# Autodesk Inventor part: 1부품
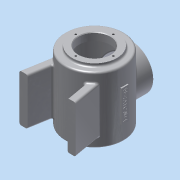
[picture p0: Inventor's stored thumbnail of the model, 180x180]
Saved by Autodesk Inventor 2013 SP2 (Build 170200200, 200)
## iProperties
Created: 2015-01
Part Number: 1부품
Material: 알루미늄 6061
Document SubType Name: Modeling
Designer: dgall
Density: 2.71 g/cm^3
Author: dgall
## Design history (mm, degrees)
sketch "스케치1"
  geometry: C1 r 50 at (0, 0); 1 further point
  constraints: 1 centre point, 1 coincident
  dimensions: "d4" = 100 diameter of C1
extrude "돌출1" new body sketch "스케치1" distance "d1" = 112; taper "d2" = 0 deg
node "작업 평면1"
sketch "스케치2"
  geometry: C1 r 38 at (0, 0); 1 further point
  constraints: 1 centre point, 1 coincident
  dimensions: "d7" = 38 radius of C1
extrude "돌출2" join sketch "스케치2" distance "d9" = 122; taper "d10" = 0 deg
sketch "스케치3"
  geometry: C1 r 38 at (0, 0) reference; C2 r 27 at (0, 0)
  constraints: 1 centre point, 1 coincident
  dimensions: "d11" = 27 radius of C2
extrude "돌출3" cut sketch "스케치3" distance "d12" = 122; taper "d13" = 0 deg
node "작업 평면2"
sketch "스케치4"
  geometry: C1 r 45 at (0, 0); 1 further point
  constraints: 1 centre point, 1 coincident
  dimensions: "d15" = 45 radius of C1
extrude "돌출4" cut sketch "스케치4" distance "d16" = 97; taper "d17" = 0 deg
node "작업 평면3"
sketch "스케치5"
  geometry: L1 (-38, 117)-(38, 117) reference; L2 (-50, 0)-(-50, 112) reference; C1 r 38 at (0, 55); 3 further points
  constraints: 2 midpoint, 1 centre point, 1 vertical alignment
  dimensions: "d81" = 38 radius of C1; "d82" = 62 distance from line of L1 C1.centre
extrude "돌출5" join sketch "스케치5" stored distance "d20" = 97; taper "d21" = 0 deg
sketch "스케치8"
  geometry: C1 r 27 at (0, 0) reference; 1 further point
  constraints: 1 vertical alignment
  dimensions: "d37" = 32 distance of C1.centre point (0, 32)
hole "구멍2" sketch "스케치8" at (0, 32) diameter "d38" = 3.242; stored, may be unused: countersink angle "d42" = 90 deg, drill point angle "d44" = 118 deg; dims "d39" = 8, "d40" = 4, "d41" = 2, "d43" = 10
node "작업 평면4"
node "작업 평면5"
sketch "스케치9"
  geometry: L1 (-38, 117)-(38, 117) reference; L2 (6, 82)-(-6, 82); L3 (-6, 82)-(-6, 28); L4 (-6, 28)-(6, 28); L5 (6, 28)-(6, 82); 5 further points
  constraints: 8 end point, 3 midpoint, 2 coincident, 2 parallel, 1 horizontal, 1 perpendicular, 1 vertical alignment
  dimensions: "d48" = 54 distance of L4.end L2.start; "d50" = 12 distance of L2.start L2.end; "d83" = 62 distance from line of L1 point (6, 55)
extrude "돌출7" join sketch "스케치9" distance "d51" = 2; taper "d52" = 0 deg
sketch "스케치11"
  geometry: L1 (-82, 6)-(-82, -6) reference; L2 (-28, 6)-(-82, 6) reference; 4 further points
  constraints: 2 midpoint, 1 horizontal alignment, 1 vertical alignment, 1 other
feature "엠보싱1" sketch "스케치11" dims "d4" = 100, "d53" = 0.5, "d54" = 0
node "작업 평면6"
sketch "스케치12"
  geometry: L1 (6, 82)-(-6, 82) reference; L2 (-6, 82)-(-6, 28) reference; L3 (6, 28)-(6, 82) reference; L4 (-6, 28)-(6, 28) reference; 1 further point
extrude "돌출8" join sketch "스케치12" stored distance "d55" = 2; taper "d56" = 0 deg
node "작업 평면7"
sketch "스케치13"
  geometry: L1 (27.282, -41.901)-(34, -80); L2 (34, -80)-(48, -80); L3 (48, -80)-(39.336, -30.865); L4 (-27.282, -41.901)-(-34, -80); L5 (-34, -80)-(-48, -80); L6 (-48, -80)-(-39.336, -30.865); C1 r 45 at (0, 0) reference; A1 r 50 centre (0, 0) between (27.282, -41.901) and (39.336, -30.865) reference; 1 further point
  constraints: 12 end point, 4 point on circle, 1 collinear, 1 horizontal, 1 parallel
  dimensions: "d58" = 14 distance of L1.end L2.end; "d60" = 80 deg angle of L2 L1; "d62" = 14 distance of L4.end L5.end; "d63" = 80 deg angle of L5 L4; "d64" = 100 deg angle of L5 L6; "d65" = 80 distance from line of point (0, 0) L5; "d66" = 80 distance from line of point (0, 0) L2; "d67" = 96 distance of L2.end L5.end; "d68" = 48 horizontal distance of point (0, 0) L5.end
extrude "돌출9" join sketch "스케치13" distance "d69" = 80; taper "d70" = 0 deg
fillet "모깎기1" dims "d71" = 3
fillet "모깎기2" dims "d72" = 3
chamfer "모따기1" distance "d73" = 1; stored, may be unused: second distance "d74" = 2, angle "d75" = 45 deg
fillet "모깎기3" dims "d76" = 3
fillet "모깎기4" dims "d77" = 3
fillet "모깎기5" dims "d78" = 3
fillet "모깎기6" dims "d79" = 3
sketch "스케치14"
  geometry: C1 r 38 at (0, 0) reference; C2 r 27 at (0, 0); 1 further point
  constraints: 1 centre point, 1 coincident
  dimensions: "d84" = 27 radius of C2
extrude "돌출10" cut sketch "스케치14" stored distance "d85" = 80; taper "d86" = 0 deg
sketch "스케치15"
  geometry: C1 r 27 at (0, 0) reference; 2 further points
  constraints: 1 vertical alignment
  dimensions: "d88" = 32 distance of C1.centre point (0, 32)
hole "구멍3" sketch "스케치15" at (0, 32) diameter "d89" = 3.242; stored, may be unused: countersink angle "d93" = 90 deg, drill point angle "d95" = 118 deg; dims "d90" = 8, "d91" = 4, "d92" = 2, "d94" = 10
fillet "모깎기8" dims "d99" = 3
fillet "모깎기9" dims "d100" = 3
chamfer "모따기2" distance "d101" = 1; stored, may be unused: second distance "d102" = 2, angle "d103" = 45 deg
sketch "스케치18"
  geometry: C1 r 27 at (0, 0) reference; C2 r 45 at (0, 0) reference
extrude "돌출13" cut sketch "스케치18" distance "d108" = 1; taper "d109" = 0 deg
sketch "스케치19"
  geometry: C1 r 27 at (0, 0) reference; C2 r 45 at (0, 0) reference
extrude "돌출14" join sketch "스케치19" distance "d110" = 1; taper "d111" = 0 deg
fillet "모깎기10" dims "d112" = 3
node "솔리드1"
pattern_circular "원형 패턴2" dims angle "d46" = 360 deg
mirror "대칭1"
pattern_circular "원형 패턴3" dims angle "d97" = 360 deg
node "절단 모서리 투영1"
other parameters: "d6" = 5, "d14" = -7, "d18" = 62, "d57" = -21
